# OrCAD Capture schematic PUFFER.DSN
size A
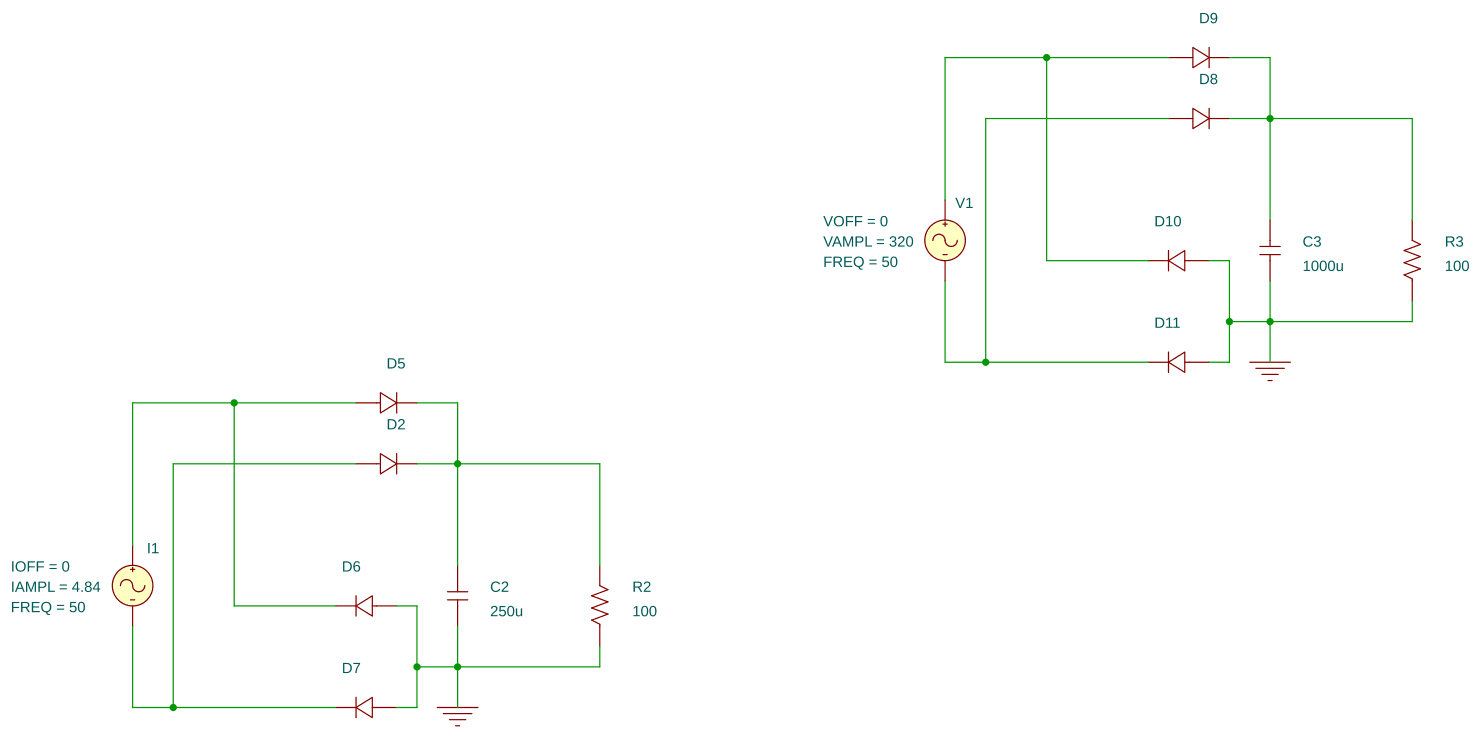
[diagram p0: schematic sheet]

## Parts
C2  250u  [RAD/CK05]
C3  1000u  [RAD/CK05]
D2  Dbreak
D5  Dbreak
D6  Dbreak
D7  Dbreak
D8  Dbreak
D9  Dbreak
D10  Dbreak
D11  Dbreak
I1  ISIN
R2  100  [AX/RC05]
R3  100  [AX/RC05]
V1  VSIN

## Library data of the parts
C2 C3 = C
D2 D5-D11 = Dbreak
I1 = ISIN: FREQ: 50; IAMPL: 4.84; IOFF: 0
R2 R3 = R
V1 = VSIN: FREQ: 50; VAMPL: 320; VOFF: 0

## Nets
0: C2.2 C3.2 D6.0(1) D7.0(1) D10.0(1) D11.0(1) R2.1 R3.1
N01393: C2.1 D2.1(2) D5.1(2) R2.2
N01949: D2.0(1) D7.1(2) I1.2(-)
N01958: D5.0(1) D6.1(2) I1.1(+)
N02421: C3.1 D8.1(2) D9.1(2) R3.2
N02589: D8.0(1) D11.1(2) V1.2(-)
N02597: D9.0(1) D10.1(2) V1.1(+)
